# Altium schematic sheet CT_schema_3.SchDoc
size 301 x 279 mm
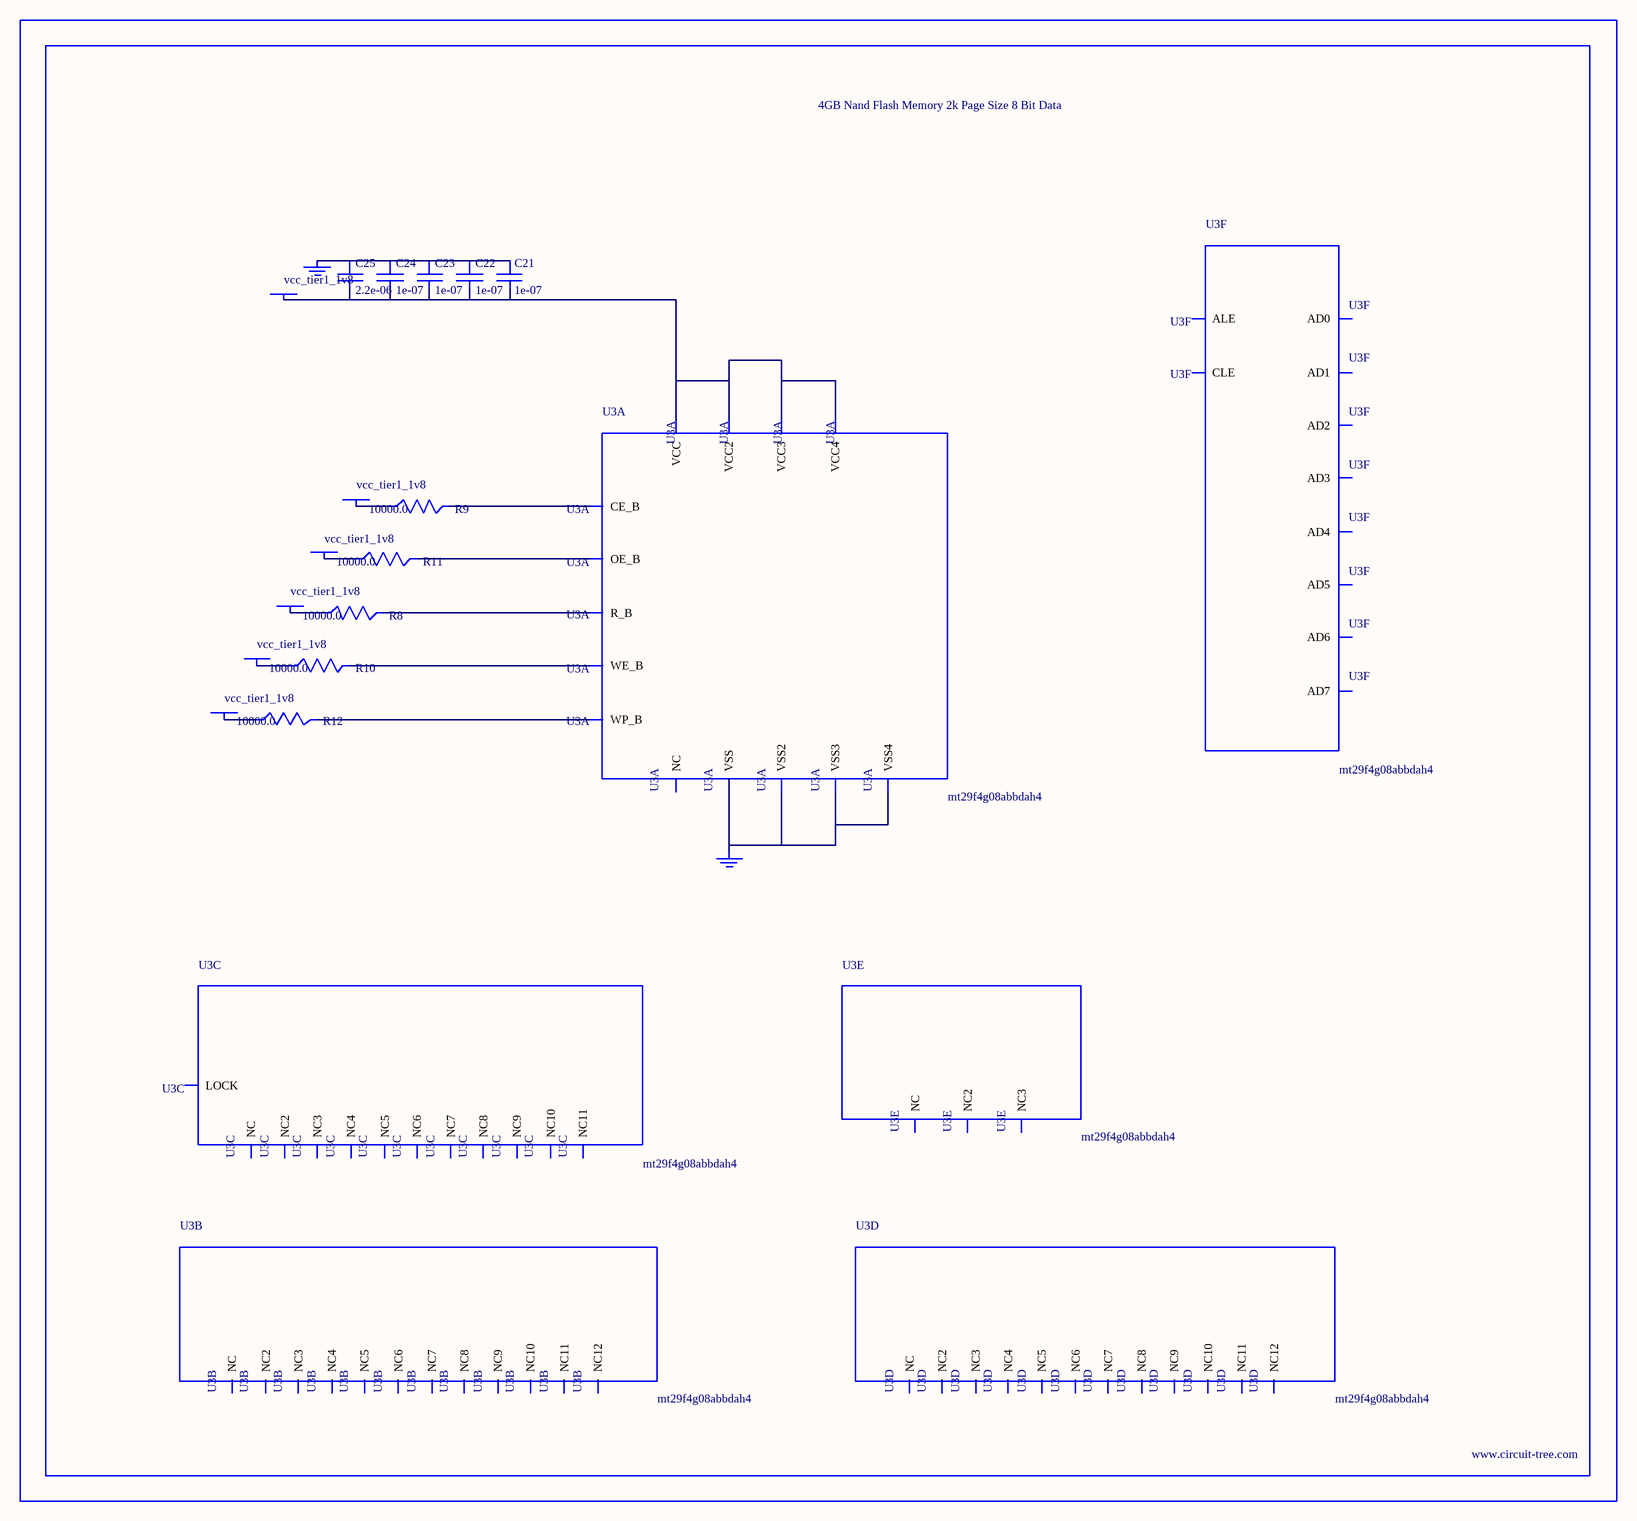
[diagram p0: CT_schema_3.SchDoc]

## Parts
BORDER2  (no value)
C21  1e-07  [C0402]
C22  1e-07  [C0402]
C23  1e-07  [C0402]
C24  1e-07  [C0402]
C25  2.2e-06  [C0603]
GND_INSTANCE_2_0  (no value)
GND_INSTANCE_2_1  (no value)
POWER_INSTANCE_2_0  vcc_tier1_1v8
POWER_INSTANCE_2_1  vcc_tier1_1v8
POWER_INSTANCE_2_2  vcc_tier1_1v8
POWER_INSTANCE_2_3  vcc_tier1_1v8
POWER_INSTANCE_2_4  vcc_tier1_1v8
POWER_INSTANCE_2_5  vcc_tier1_1v8
R8  10000.0  [R0603]
R9  10000.0  [R0603]
R10  10000.0  [R0603]
R11  10000.0  [R0603]
R12  10000.0  [R0603]
U3  mt29f4g08abbdah4  [VFBGA-63]  (parts A,B,C,D,E,F of 6)

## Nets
NetC21_1: C21.1 C22.1 C23.1 C24.1 C25.1 GND_INSTANCE_2_0.0(GND)
NetC21_2: C21.2 C22.2 C23.2 C24.2 C25.2 POWER_INSTANCE_2_0.0(PWR) U3.D3(VCC) U3.G4(VCC2) U3.H8(VCC3) U3.J6(VCC4)
NetGND_INSTANCE_2_1_0: GND_INSTANCE_2_1.0(GND) U3.C5(VSS) U3.F7(VSS2) U3.K3(VSS3) U3.K8(VSS4)
NetPOWER_INSTANCE_2_1_0: POWER_INSTANCE_2_1.0(PWR) R8.1
NetPOWER_INSTANCE_2_2_0: POWER_INSTANCE_2_2.0(PWR) R9.1
NetPOWER_INSTANCE_2_3_0: POWER_INSTANCE_2_3.0(PWR) R10.1
NetPOWER_INSTANCE_2_4_0: POWER_INSTANCE_2_4.0(PWR) R11.1
NetPOWER_INSTANCE_2_5_0: POWER_INSTANCE_2_5.0(PWR) R12.1
NetR8_2: R8.2 U3.C8(R_B)
NetR9_2: R9.2 U3.C6(CE_B)
NetR10_2: R10.2 U3.C7(WE_B)
NetR11_2: R11.2 U3.D4(OE_B)
NetR12_2: R12.2 U3.C3(WP_B)

Not connected (* = marked no-connect by the designer): U3 A1(NC) A2(NC3) A9(NC4) A10(NC2) B1(NC5) B9(NC7) B10(NC6) C4(ALE) D5(CLE) D6(NC8) D7(NC9) D8(NC10) E3(NC11) E4(NC12) E5(NC) E6(NC2) E7(NC3) E8(NC4) F3(NC5) F4(NC6) F5(NC7) F6(NC8) F8(NC9) G3(NC) G5(LOCK) G6(NC10) G7(NC11) G8(NC) H3(NC2) H4(AD0) H5(NC3) H6(NC4) H7(NC5) J3(NC6) J4(AD1) J5(NC7) J7(AD5) J8(AD7) K4(AD2) K5(AD3) K6(AD4) K7(AD6) L1(NC8) L2(NC10) L9(NC11) L10(NC9) M1(NC12) M2(NC2) M9(NC3) M10(NC)

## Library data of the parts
BORDER2 = BORDER_PAGE2
C21-C24 = C0402C104K3RACTU
C25 = C0603C225K8RACTU
GND_INSTANCE_2_0 GND_INSTANCE_2_1 = GND
POWER_INSTANCE_2_0-POWER_INSTANCE_2_5 = PWR
R8-R12 = RC0603JR-0710KL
